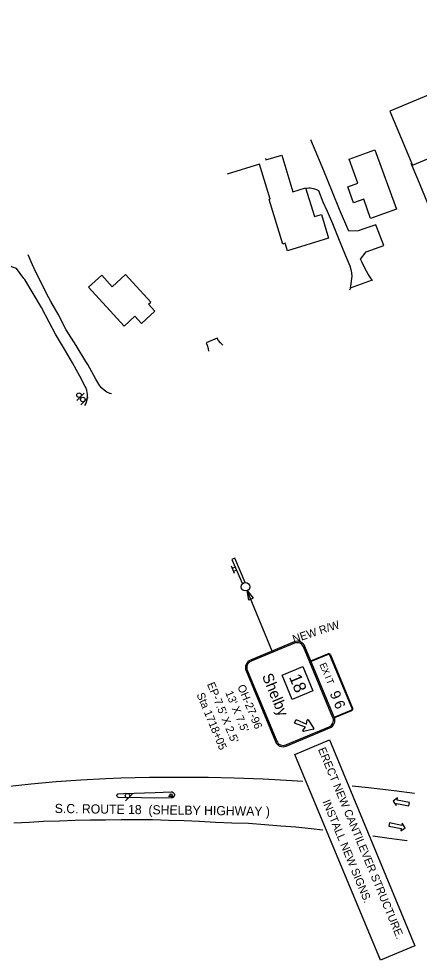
# Model space of a CAD drawing. Extents: x 1817507 to 1819117, y 1191678 to 1192982.
# Drawn here: x 1818204 to 1818554, y 1191881 to 1192705 of the extents above; entities that cross this region are included whole.
import ezdxf

# ---------------------------------------------------------------- set-up
doc = ezdxf.new("R2010")
doc.units = 0
for name, color, linetype in [('RD_EX_Bldg', 7, 'Continuous'), ('RD_EX_Road', 7, 'Continuous'), ('RD_PD_Final_LnLine', 7, 'Continuous'), ('RD_PD_RW_TX', 7, 'Continuous'), ('RD_TX_RoadID', 7, 'Continuous'), ('SN_P_Signs', 7, 'Continuous')]:
    doc.layers.add(name, color=color, linetype=linetype)

# ---------------------------------------------------------------- blocks, each defined once
blk = doc.blocks.new('SARRW2')
at = {"layer": 'RD_PD_Final_LnLine'}
blk.add_lwpolyline([(-12, 1.2), (-12, -1.2), (-2.83, -1.2), (-2.83, -2.83), (0, 0), (-2.83, 2.83), (-2.83, 1.2)], close=True, dxfattribs=at)

msp = doc.modelspace()

# ---------------------------------------------------------------- linework, layer by layer
at = {"layer": 'RD_EX_Bldg'}
for points in [[(1818528.67, 1192624.18), (1818548.42, 1192576.83), (1818741.98, 1192657.6), (1818722.22, 1192704.95), (1818528.67, 1192624.18)], [(1818419.72, 1192582.76), (1818420.09, 1192581.55), (1818434.01, 1192585.79), (1818443.81, 1192553.64), (1818454.92, 1192557.03), (1818462.57, 1192531.94), (1818468.72, 1192533.81), (1818475.08, 1192512.94), (1818439.15, 1192501.99)], [(1818511.83, 1192530.36), (1818505.79, 1192547.08), (1818496.9, 1192543.86), (1818491.83, 1192557.91), (1818500.57, 1192561.06), (1818492.94, 1192582.19), (1818515.66, 1192590.4), (1818534.4, 1192538.51), (1818511.83, 1192530.36)], [(1818439.15, 1192501.99), (1818437.16, 1192508.52), (1818434.86, 1192507.82), (1818422.95, 1192546.88), (1818423.93, 1192547.18), (1818414.6, 1192577.79), (1818386.28, 1192569.15)], [(1818264.95, 1192470.08), (1818295.9, 1192436.16), (1818305.32, 1192444.75), (1818311.19, 1192438.32), (1818322.97, 1192449.07), (1818317.27, 1192455.31), (1818319.3, 1192457.16), (1818297.26, 1192481.32), (1818285.47, 1192470.56), (1818276.39, 1192480.51), (1818264.95, 1192470.08)]]:
    msp.add_lwpolyline(points, dxfattribs=at)
at = {"layer": 'RD_EX_Road'}
for points in [[(1818513.21, 1192476.3), (1818509.62, 1192481.5), (1818506.65, 1192486.8), (1818504.03, 1192492.28), (1818503.07, 1192494.53), (1818507.95, 1192500.97), (1818523.53, 1192506.73), (1818516.32, 1192524.75), (1818505.86, 1192521.23), (1818500.99, 1192519.53), (1818492.63, 1192519.18), (1818484.67, 1192538.01), (1818478.49, 1192553.35), (1818470.8, 1192571.84), (1818461.73, 1192593.5), (1818459.54, 1192598.98)], [(1818606.51, 1192514.58), (1818605.33, 1192521.69), (1818597.26, 1192532.91), (1818570.76, 1192521.95), (1818566.24, 1192532.56), (1818559.46, 1192549.88), (1818553.27, 1192564.53), (1818547.41, 1192578.46)], [(1818455.08, 1192556.5), (1818455.93, 1192556.83), (1818457.82, 1192557.17), (1818459.03, 1192557.18), (1818461.77, 1192556.57), (1818464.39, 1192555.59), (1818466.18, 1192554.65), (1818470.09, 1192544.86), (1818473.8, 1192536.71), (1818478.39, 1192525.86), (1818483.76, 1192512.8), (1818489.54, 1192498.35), (1818493.51, 1192488.77), (1818494.47, 1192485.73), (1818495.06, 1192482.58), (1818495.25, 1192479.39), (1818495.21, 1192477.96), (1818494.57, 1192472.97), (1818493.82, 1192469.37)], [(1818284.98, 1192376.94), (1818283.9, 1192377.1), (1818283.49, 1192377.25), (1818280.98, 1192378.42), (1818278.66, 1192379.93), (1818276.58, 1192381.76), (1818274.79, 1192383.87), (1818271.31, 1192389.7), (1818264.22, 1192402.38), (1818262.61, 1192405.12), (1818254.15, 1192419.06), (1818245.35, 1192432.79), (1818238.19, 1192446.43), (1818231.91, 1192457.73), (1818229.84, 1192461.44), (1818224.82, 1192470.96), (1818220.16, 1192480.66), (1818218.44, 1192483.97), (1818214.49, 1192492.18), (1818211.85, 1192498.33)], [(1818261.58, 1192366.73), (1818262.42, 1192368.15), (1818263.13, 1192369.69), (1818263.78, 1192371.95), (1818264.05, 1192374.28), (1818263.92, 1192376.63), (1818263.72, 1192377.76), (1818263.24, 1192380.13), (1818262.38, 1192382.4), (1818261.87, 1192383.37), (1818257.12, 1192392.2), (1818250.7, 1192404.08), (1818244.61, 1192414.31), (1818236, 1192429.02), (1818230.42, 1192439.59), (1818223.55, 1192452.27), (1818216.46, 1192464.6), (1818209.02, 1192476.73), (1818208.32, 1192477.83), (1818201.84, 1192486.47), (1818198.24, 1192487.72), (1818194.24, 1192489.73), (1818193.11, 1192490.73)], [(1818513.51, 1192475.93), (1818513.21, 1192476.3), (1818493.82, 1192469.37), (1818493.54, 1192468.04), (1818493.4, 1192467.57)], [(1818382.57, 1192419.51), (1818382.08, 1192419.83), (1818380.27, 1192421.48), (1818378.74, 1192423.4), (1818377.55, 1192425.55), (1818367.98, 1192421.42), (1818368.23, 1192420.85), (1818368.79, 1192419.41), (1818369.62, 1192416.49), (1818369.99, 1192414.02)], [(1818452.39, 1192037.52), (1818443.02, 1192038.23), (1818417.72, 1192039.64), (1818392.4, 1192040.65), (1818369.9, 1192041.22), (1818368.08, 1192041.03), (1818343.1, 1192041.21), (1818318.12, 1192041), (1818293.15, 1192040.4), (1818280.06, 1192039.92), (1818258.22, 1192038.75), (1818236.4, 1192037.19), (1818214.62, 1192035.23), (1818192.87, 1192032.88)], [(1818550.21, 1192027.11), (1818532.33, 1192029.53), (1818509.94, 1192032.21), (1818495.57, 1192033.66)], [(1818311.27, 1192023.2), (1818291.2, 1192023.54), (1818290.44, 1192023.91), (1818289.92, 1192024.58), (1818289.76, 1192025.41), (1818289.98, 1192026.23), (1818290.54, 1192026.86), (1818290.68, 1192026.94), (1818295.44, 1192027.12), (1818323.18, 1192027.95), (1818337.16, 1192028.53), (1818338.18, 1192028.45), (1818339.09, 1192027.99), (1818339.77, 1192027.22), (1818340.12, 1192026.26), (1818340.07, 1192025.24), (1818339.65, 1192024.31), (1818338.91, 1192023.6), (1818337.96, 1192023.22), (1818337.12, 1192023.19), (1818322.45, 1192023.05), (1818311.27, 1192023.2)], [(1818199.49, 1192001.44), (1818212.84, 1192002.06), (1818225.48, 1192002.83), (1818239.35, 1192003.34), (1818253.02, 1192003.7), (1818266.47, 1192004.11), (1818279.78, 1192004.17), (1818293.55, 1192004.37), (1818307.26, 1192004.32), (1818320.77, 1192004.27), (1818334.75, 1192003.7), (1818348.62, 1192003.5), (1818362.03, 1192002.83), (1818375.95, 1192002.16), (1818390.33, 1192001.49), (1818404.77, 1192001.14), (1818419.25, 1191999.9), (1818433.17, 1191998.93), (1818446.38, 1191997.8), (1818459.89, 1191996.51), (1818469.89, 1191995.43)], [(1818513.68, 1191990.1), (1818525.95, 1191988.45), (1818539.31, 1191986.55), (1818543.92, 1191985.97)]]:
    msp.add_lwpolyline(points, dxfattribs=at)
at = {"layer": 'SN_P_Signs'}
for p, q in [((1818254.71, 1192371), (1818261.07, 1192377.37)), ((1818258.06, 1192367.27), (1818264.42, 1192373.64)), ((1818392.63, 1192219.57), (1818389.89, 1192225.96)), ((1818393.28, 1192225.05), (1818390.72, 1192223.95)), ((1818394.33, 1192222.59), (1818391.79, 1192221.5)), ((1818425.72, 1192151.79), (1818403.75, 1192204.64)), ((1818445.25, 1192158.61), (1818407.11, 1192142.76)), ((1818434.27, 1192130.62), (1818452.45, 1192138.18)), ((1818443.12, 1192109.32), (1818434.27, 1192130.62)), ((1818461.3, 1192116.88), (1818443.12, 1192109.32)), ((1818437.47, 1192069.69), (1818475.62, 1192085.54)), ((1818445.55, 1192061.34), (1818475.84, 1192073.93)), ((1818475.84, 1192073.93), (1818550.67, 1191893.86)), ((1818520.38, 1191881.27), (1818445.55, 1192061.34)), ((1818297.16, 1192020.62), (1818303.52, 1192026.98)), ((1818334.86, 1192024.75), (1818339.36, 1192024.75)), ((1818550.67, 1191893.86), (1818520.38, 1191881.27))]:
    msp.add_line(p, q, dxfattribs=at)
for points in [[(1818402.01, 1192211.77), (1818392.89, 1192233.02), (1818390.33, 1192231.92), (1818399.52, 1192210.5)], [(1818444.79, 1192159.71), (1818406.65, 1192143.86)], [(1818478.85, 1192093.38), (1818453.09, 1192155.37)], [(1818479.96, 1192093.84), (1818454.2, 1192155.83)], [(1818474.66, 1192148.82), (1818459.7, 1192142.6), (1818459.47, 1192143.16), (1818474.43, 1192149.37)], [(1818495.57, 1192101.63), (1818476.23, 1192148.17)], [(1818476.78, 1192148.4), (1818496.12, 1192101.86)], [(1818452.45, 1192138.18), (1818461.3, 1192116.88)], [(1818402.76, 1192134.45), (1818428.52, 1192072.47)], [(1818403.87, 1192134.91), (1818429.63, 1192072.93)], [(1818479.96, 1192093.84), (1818494.92, 1192100.06)], [(1818495.15, 1192099.51), (1818480.19, 1192093.29), (1818479.96, 1192093.84)], [(1818445.3, 1192088.57), (1818446.68, 1192091.9), (1818455.8, 1192087.65)], [(1818454.77, 1192085.15), (1818445.3, 1192088.57)], [(1818455.8, 1192087.65), (1818456.34, 1192091.28)], [(1818457.16, 1192091.47), (1818462.17, 1192083.96)], [(1818437.93, 1192068.58), (1818476.08, 1192084.43)], [(1818452.59, 1192082.19), (1818454.77, 1192085.15)], [(1818461.89, 1192083.27), (1818453.04, 1192081.49)]]:
    msp.add_lwpolyline(points, dxfattribs=at)
msp.add_lwpolyline([(1818405.14, 1192196.31), (1818403.79, 1192204.66), (1818408.91, 1192197.93)], close=True, dxfattribs=at)
for centre, radius in [((1818256.47, 1192375.63), 2), ((1818259.82, 1192371.9), 2), ((1818402.33, 1192208.07), 3.71), ((1818298.92, 1192025.25), 2), ((1818337.12, 1192025.76), 1)]:
    msp.add_circle(centre, radius, dxfattribs=at)
for centre, radius, start, end in [((1818447.55, 1192153.07), 7.2, 22.56659, 112.56659), ((1818447.55, 1192153.07), 6, 22.56659, 112.56659), ((1818475.12, 1192147.71), 1.8, 22.56659, 112.56659), ((1818475.12, 1192147.71), 1.2, 22.56659, 112.56659), ((1818409.41, 1192137.21), 7.2, 112.56659, 202.56659), ((1818409.41, 1192137.21), 6, 112.56659, 202.56659), ((1818494.46, 1192101.17), 1.2, 292.56659, 22.56659), ((1818494.46, 1192101.17), 1.8, 292.56659, 22.56659), ((1818456.78, 1192091.22), 0.45, 33.74449, 171.52869), ((1818473.31, 1192091.08), 6, 292.56659, 22.56659), ((1818473.31, 1192091.08), 7.2, 292.56659, 22.56659), ((1818452.95, 1192081.93), 0.45, 143.60449, 281.38869), ((1818461.8, 1192083.71), 0.45, 281.38869, 33.74449), ((1818435.17, 1192075.23), 7.2, 202.56659, 292.56659), ((1818435.17, 1192075.23), 6, 202.56659, 292.56659)]:
    msp.add_arc(centre, radius, start, end, dxfattribs=at)

# ---------------------------------------------------------------- block references
at = {"layer": 'RD_PD_Final_LnLine'}
for p, xscale, yscale, rotation in [((1818531.5, 1192020.53), 1.2000000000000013, 1.2, 168.8968269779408), ((1818542.24, 1191997.16), 1.200000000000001, 1.2000000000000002, -11.103173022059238)]:
    msp.add_blockref('SARRW2', p, dxfattribs=dict(at, xscale=xscale, yscale=yscale, rotation=rotation))

# ---------------------------------------------------------------- texts
at = {"layer": 'RD_PD_RW_TX'}
msp.add_text('NEW R/W', height=7, rotation=18.36998, dxfattribs=at).set_placement((1818444.82, 1192158.66))
at = {"layer": 'RD_TX_RoadID'}
msp.add_text('S.C. ROUTE 18  (SHELBY HIGHWAY )', height=8, rotation=359.21456, dxfattribs=at).set_placement((1818235.21, 1192010.08))
at = {"layer": 'SN_P_Signs'}
for s, height, rotation, p in [('E', 6, 292.56659, (1818466.93, 1192140.05)), ('Shelby', 9.6, 292.56659, (1818416.55, 1192129.95)), ('18', 10.8, 292.56659, (1818440.15, 1192129.05)), ('X', 6, 292.56659, (1818468.91, 1192135.29)), ('I', 6, 292.56659, (1818471.53, 1192129)), ("EP-7.5' X 2.5'", 7, 292.56667, (1818368.43, 1192122.81)), ('OH-27-96', 7, 292.56667, (1818395.06, 1192120.75)), ('T', 6, 292.56659, (1818472.67, 1192126.24)), ('Sta 1718+05', 7, 292.56667, (1818359.32, 1192113.72)), ("13' X 7.5'", 7, 292.56667, (1818384.41, 1192115.37)), ('9', 9, 292.56659, (1818475.84, 1192114.7)), ('6', 9, 292.56659, (1818479.33, 1192106.3)), ('ERECT NEW CANTILEVER STRUCTURE.', 7, 292.56667, (1818465.65, 1192065.76)), ('INSTALL NEW SIGNS.', 7, 292.56667, (1818469.51, 1192019.99))]:
    msp.add_text(s, height=height, rotation=rotation, dxfattribs=at).set_placement(p)

doc.saveas('drawing.dxf')
